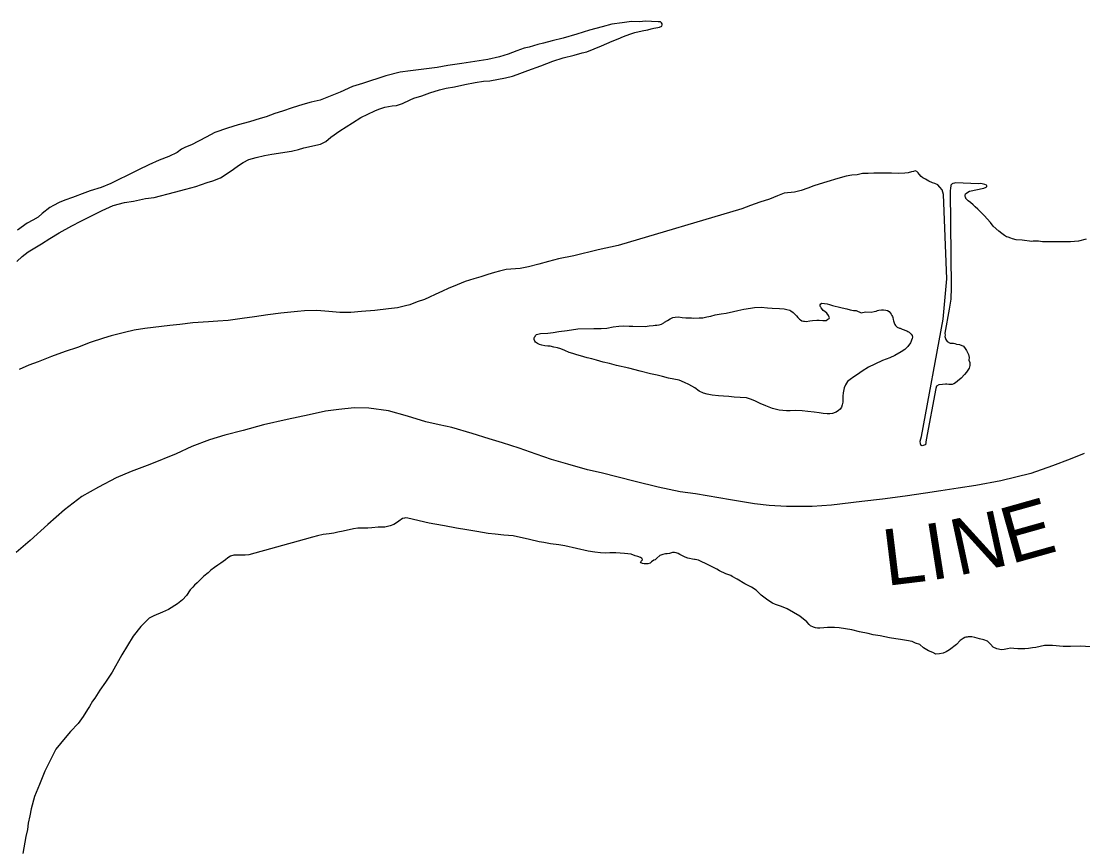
# Model space of a CAD drawing. Extents: x -939622 to -934222, y 1383701 to 1385301.
# Drawn here: x -935792.07 to -935768.16, y 1383906.21 to 1383924.82 of the extents above; entities that cross this region are included whole.
import ezdxf

# ---------------------------------------------------------------- set-up
doc = ezdxf.new("R2010")
doc.units = 0
doc.layers.add('Level 3', color=7, linetype='Continuous')
doc.layers.add('Level 9', color=7, linetype='Continuous')

msp = doc.modelspace()

# ---------------------------------------------------------------- linework, layer by layer
at = {"layer": 'Level 3'}
msp.add_lwpolyline([(-935768.121, 1383915.075), (-935768.44, 1383914.945), (-935768.84, 1383914.8), (-935769.329, 1383914.621), (-935769.999, 1383914.456), (-935770.566, 1383914.355), (-935770.963, 1383914.291), (-935771.352, 1383914.237), (-935771.698, 1383914.181), (-935772.155, 1383914.115), (-935772.664, 1383914.049), (-935773.133, 1383913.992), (-935773.818, 1383913.911), (-935774.253, 1383913.881), (-935774.833, 1383913.882), (-935775.222, 1383913.906), (-935775.55, 1383913.938), (-935776.089, 1383914.028), (-935776.882, 1383914.163), (-935777.226, 1383914.209), (-935777.717, 1383914.316), (-935778.242, 1383914.443), (-935779.004, 1383914.642), (-935779.31, 1383914.708), (-935779.754, 1383914.835), (-935780.125, 1383914.943), (-935780.469, 1383915.062), (-935780.853, 1383915.198), (-935781.225, 1383915.318), (-935781.526, 1383915.406), (-935781.909, 1383915.526), (-935782.365, 1383915.659), (-935782.653, 1383915.725), (-935782.953, 1383915.792), (-935783.37, 1383915.914), (-935783.798, 1383916.035), (-935784.24, 1383916.096), (-935784.567, 1383916.104), (-935784.918, 1383916.069), (-935785.211, 1383916.028), (-935785.583, 1383915.947), (-935786.081, 1383915.84), (-935786.614, 1383915.719), (-935787.072, 1383915.596), (-935787.482, 1383915.486), (-935787.83, 1383915.382), (-935788.227, 1383915.231), (-935788.575, 1383915.07), (-935789.172, 1383914.824), (-935789.593, 1383914.672), (-935789.93, 1383914.526), (-935790.325, 1383914.318), (-935790.707, 1383914.104), (-935791.092, 1383913.809), (-935791.473, 1383913.475), (-935791.867, 1383913.113), (-935792.184, 1383912.848)], dxfattribs=at)
at = {"layer": 'Level 9'}
for points in [[(-935779.329, 1383924.128), (-935778.997, 1383924.261), (-935778.758, 1383924.367), (-935778.622, 1383924.418), (-935778.498, 1383924.468), (-935778.358, 1383924.521), (-935778.243, 1383924.559), (-935778.148, 1383924.584), (-935778.046, 1383924.606), (-935777.951, 1383924.625), (-935777.882, 1383924.643), (-935777.82, 1383924.66), (-935777.73, 1383924.676), (-935777.689, 1383924.683), (-935777.635, 1383924.704), (-935777.634, 1383924.734), (-935777.631, 1383924.758), (-935777.644, 1383924.781), (-935777.669, 1383924.802), (-935777.723, 1383924.799), (-935777.874, 1383924.812), (-935778.006, 1383924.815), (-935778.138, 1383924.804), (-935778.325, 1383924.806), (-935778.531, 1383924.78), (-935778.761, 1383924.746), (-935778.984, 1383924.689), (-935779.267, 1383924.612), (-935779.552, 1383924.525), (-935779.861, 1383924.435), (-935780.111, 1383924.371), (-935780.301, 1383924.321), (-935780.429, 1383924.292), (-935780.628, 1383924.233), (-935780.738, 1383924.205), (-935780.901, 1383924.147), (-935781.097, 1383924.07), (-935781.293, 1383924.014), (-935781.555, 1383923.956), (-935782.146, 1383923.866), (-935782.46, 1383923.815), (-935782.696, 1383923.775), (-935782.998, 1383923.736), (-935783.3, 1383923.7), (-935783.53, 1383923.664), (-935783.855, 1383923.588), (-935784.38, 1383923.414), (-935784.605, 1383923.342), (-935784.883, 1383923.219), (-935785.336, 1383923.039), (-935785.538, 1383922.995), (-935785.722, 1383922.939), (-935785.966, 1383922.863), (-935786.186, 1383922.791), (-935786.358, 1383922.734), (-935786.55, 1383922.663), (-935786.684, 1383922.621), (-935786.927, 1383922.551), (-935787.183, 1383922.484), (-935787.42, 1383922.403), (-935787.708, 1383922.307), (-935787.906, 1383922.206), (-935788.235, 1383922.033), (-935788.372, 1383921.98), (-935788.457, 1383921.931), (-935788.559, 1383921.861), (-935788.745, 1383921.769), (-935788.964, 1383921.685), (-935789.194, 1383921.58), (-935789.43, 1383921.468), (-935789.681, 1383921.338), (-935789.872, 1383921.246), (-935790.052, 1383921.158), (-935790.268, 1383921.071), (-935790.515, 1383920.992), (-935790.639, 1383920.948), (-935790.915, 1383920.847), (-935791.083, 1383920.78), (-935791.214, 1383920.73), (-935791.343, 1383920.667), (-935791.423, 1383920.619), (-935791.594, 1383920.48), (-935791.691, 1383920.401), (-935791.805, 1383920.336), (-935791.932, 1383920.265), (-935792.154, 1383920.106)], [(-935792.168, 1383919.398), (-935792.046, 1383919.517), (-935791.912, 1383919.622), (-935791.613, 1383919.802), (-935791.422, 1383919.918), (-935791.211, 1383920.047), (-935790.931, 1383920.202), (-935790.725, 1383920.313), (-935790.531, 1383920.408), (-935790.248, 1383920.551), (-935789.997, 1383920.663), (-935789.741, 1383920.728), (-935789.538, 1383920.763), (-935789.27, 1383920.822), (-935789.072, 1383920.847), (-935788.617, 1383920.962), (-935788.361, 1383921.035), (-935788.132, 1383921.092), (-935787.88, 1383921.183), (-935787.75, 1383921.222), (-935787.581, 1383921.289), (-935787.449, 1383921.372), (-935787.288, 1383921.481), (-935787.174, 1383921.561), (-935787.072, 1383921.631), (-935786.945, 1383921.696), (-935786.773, 1383921.748), (-935786.588, 1383921.791), (-935786.424, 1383921.819), (-935785.979, 1383921.888), (-935785.949, 1383921.898), (-935785.821, 1383921.927), (-935785.705, 1383921.962), (-935785.33, 1383922.046), (-935785.209, 1383922.105), (-935785.092, 1383922.2), (-935784.891, 1383922.349), (-935784.609, 1383922.523), (-935784.419, 1383922.648), (-935784.103, 1383922.799), (-935784.011, 1383922.835), (-935783.881, 1383922.877), (-935783.711, 1383922.907), (-935783.612, 1383922.92), (-935783.481, 1383922.962), (-935783.307, 1383923.044), (-935783.222, 1383923.08), (-935783.046, 1383923.135), (-935782.863, 1383923.203), (-935782.649, 1383923.268), (-935782.494, 1383923.305), (-935782.306, 1383923.336), (-935782.077, 1383923.387), (-935781.841, 1383923.436), (-935781.659, 1383923.464), (-935781.512, 1383923.476), (-935781.157, 1383923.541), (-935781.002, 1383923.58), (-935780.895, 1383923.612), (-935780.653, 1383923.705), (-935780.365, 1383923.813), (-935780.096, 1383923.917), (-935779.861, 1383923.99), (-935779.614, 1383924.05), (-935779.43, 1383924.1), (-935779.329, 1383924.128)], [(-935771.421, 1383921.127), (-935771.491, 1383921.157), (-935771.543, 1383921.173), (-935771.626, 1383921.215), (-935771.697, 1383921.254), (-935771.758, 1383921.288), (-935771.795, 1383921.32), (-935771.842, 1383921.369), (-935771.862, 1383921.401), (-935771.893, 1383921.427), (-935771.929, 1383921.441), (-935771.968, 1383921.433), (-935772.01, 1383921.419), (-935772.087, 1383921.401), (-935772.165, 1383921.389), (-935772.306, 1383921.387), (-935772.465, 1383921.389), (-935772.61, 1383921.393), (-935772.724, 1383921.391), (-935772.859, 1383921.389), (-935772.988, 1383921.384), (-935773.114, 1383921.382), (-935773.236, 1383921.356), (-935773.356, 1383921.345), (-935773.487, 1383921.325), (-935773.672, 1383921.275), (-935773.921, 1383921.199), (-935774.096, 1383921.144), (-935774.212, 1383921.107), (-935774.351, 1383921.056), (-935774.497, 1383921.005), (-935774.619, 1383920.973), (-935774.648, 1383920.963), (-935774.879, 1383920.939), (-935775.033, 1383920.879), (-935775.216, 1383920.808), (-935775.433, 1383920.736), (-935775.637, 1383920.662), (-935775.836, 1383920.591), (-935778.619, 1383919.765), (-935779.069, 1383919.663), (-935779.617, 1383919.527), (-935779.966, 1383919.459), (-935780.192, 1383919.401), (-935780.412, 1383919.342), (-935780.644, 1383919.284), (-935780.829, 1383919.247), (-935781.144, 1383919.222), (-935781.292, 1383919.186), (-935781.408, 1383919.155), (-935781.56, 1383919.11), (-935781.714, 1383919.058), (-935781.872, 1383919.01), (-935782.071, 1383918.951), (-935782.245, 1383918.878), (-935782.449, 1383918.792), (-935782.582, 1383918.732), (-935782.744, 1383918.659), (-935782.874, 1383918.6), (-935782.983, 1383918.548), (-935783.146, 1383918.49), (-935783.315, 1383918.426), (-935783.416, 1383918.401), (-935783.595, 1383918.355), (-935783.792, 1383918.332), (-935784.101, 1383918.296), (-935784.403, 1383918.272), (-935784.643, 1383918.25), (-935784.892, 1383918.253), (-935785.137, 1383918.276), (-935785.411, 1383918.295), (-935785.684, 1383918.293), (-935785.846, 1383918.278), (-935786.22, 1383918.239), (-935786.51, 1383918.198), (-935786.815, 1383918.156), (-935787.09, 1383918.115), (-935787.41, 1383918.075), (-935787.643, 1383918.054), (-935787.853, 1383918.039), (-935788.201, 1383918.019), (-935788.497, 1383917.981), (-935788.718, 1383917.957), (-935789.281, 1383917.893), (-935789.526, 1383917.853), (-935789.746, 1383917.799), (-935790.044, 1383917.727), (-935790.213, 1383917.675), (-935790.513, 1383917.576), (-935790.803, 1383917.465), (-935791.079, 1383917.373), (-935791.384, 1383917.262), (-935791.686, 1383917.144), (-935791.899, 1383917.064), (-935792.112, 1383916.965)], [(-935769.306, 1383919.853), (-935769.524, 1383919.88), (-935769.657, 1383919.893), (-935769.736, 1383919.914), (-935769.778, 1383919.924), (-935769.836, 1383919.952), (-935769.873, 1383919.96), (-935769.922, 1383919.985), (-935769.981, 1383920.031), (-935770.046, 1383920.085), (-935770.176, 1383920.195), (-935770.234, 1383920.283), (-935770.309, 1383920.361), (-935770.372, 1383920.431), (-935770.435, 1383920.5), (-935770.519, 1383920.578), (-935770.581, 1383920.636), (-935770.628, 1383920.682), (-935770.687, 1383920.731), (-935770.737, 1383920.765), (-935770.777, 1383920.806), (-935770.783, 1383920.809), (-935770.8, 1383920.85), (-935770.804, 1383920.865), (-935770.805, 1383920.895), (-935770.794, 1383920.923), (-935770.777, 1383920.944), (-935770.747, 1383920.964), (-935770.706, 1383920.983), (-935770.387, 1383921.053), (-935770.328, 1383921.073), (-935770.317, 1383921.089), (-935770.314, 1383921.104), (-935770.327, 1383921.122), (-935770.358, 1383921.139), (-935770.451, 1383921.156), (-935770.505, 1383921.151), (-935771.023, 1383921.172), (-935771.047, 1383921.165), (-935771.086, 1383921.158), (-935771.101, 1383921.154), (-935771.115, 1383921.136), (-935771.126, 1383921.12), (-935771.131, 1383921.099), (-935771.136, 1383921.06), (-935771.139, 1383920.987), (-935771.12, 1383918.812), (-935771.128, 1383918.553), (-935771.164, 1383918.329), (-935771.26, 1383917.786), (-935771.258, 1383917.744), (-935771.263, 1383917.711), (-935771.256, 1383917.687), (-935771.239, 1383917.645), (-935771.226, 1383917.622), (-935771.207, 1383917.601), (-935771.143, 1383917.559), (-935771.068, 1383917.559), (-935771.034, 1383917.557), (-935771.001, 1383917.54), (-935770.934, 1383917.534), (-935770.846, 1383917.495), (-935770.802, 1383917.443), (-935770.772, 1383917.393), (-935770.759, 1383917.366), (-935770.733, 1383917.307), (-935770.718, 1383917.239), (-935770.719, 1383917.178), (-935770.702, 1383917.125), (-935770.699, 1383917.059), (-935770.715, 1383917.001), (-935770.726, 1383916.973), (-935770.772, 1383916.911), (-935770.82, 1383916.855), (-935770.898, 1383916.771), (-935770.974, 1383916.702), (-935771.023, 1383916.667), (-935771.059, 1383916.644), (-935771.097, 1383916.628), (-935771.172, 1383916.628), (-935771.221, 1383916.635), (-935771.251, 1383916.637), (-935771.316, 1383916.628), (-935771.4, 1383916.622), (-935771.447, 1383916.59), (-935771.469, 1383916.541), (-935771.682, 1383915.386), (-935771.702, 1383915.273), (-935771.729, 1383915.263), (-935771.752, 1383915.253), (-935771.773, 1383915.249), (-935771.798, 1383915.258), (-935771.811, 1383915.296), (-935771.816, 1383915.35), (-935771.787, 1383915.46), (-935771.302, 1383918.1), (-935771.221, 1383919.01), (-935771.292, 1383920.912), (-935771.321, 1383921.016), (-935771.377, 1383921.074), (-935771.421, 1383921.127)], [(-935768.079, 1383919.901), (-935768.255, 1383919.861), (-935768.434, 1383919.842), (-935768.594, 1383919.842), (-935768.729, 1383919.842), (-935768.9, 1383919.848), (-935769.063, 1383919.847), (-935769.156, 1383919.856), (-935769.271, 1383919.86), (-935769.306, 1383919.853)], [(-935777.648, 1383917.988), (-935777.592, 1383918.017), (-935777.575, 1383918.033), (-935777.513, 1383918.072), (-935777.454, 1383918.107), (-935777.387, 1383918.14), (-935777.339, 1383918.148), (-935777.261, 1383918.151), (-935777.182, 1383918.136), (-935777.101, 1383918.13), (-935776.968, 1383918.132), (-935776.914, 1383918.128), (-935776.8, 1383918.13), (-935776.713, 1383918.133), (-935776.627, 1383918.155), (-935776.537, 1383918.17), (-935776.433, 1383918.199), (-935776.299, 1383918.222), (-935776.188, 1383918.241), (-935776.027, 1383918.272), (-935775.929, 1383918.294), (-935775.792, 1383918.326), (-935775.64, 1383918.35), (-935775.553, 1383918.363), (-935775.403, 1383918.369), (-935775.255, 1383918.36), (-935775.153, 1383918.349), (-935774.99, 1383918.34), (-935774.885, 1383918.335), (-935774.821, 1383918.319), (-935774.757, 1383918.304), (-935774.733, 1383918.287), (-935774.68, 1383918.256), (-935774.649, 1383918.224), (-935774.605, 1383918.181), (-935774.576, 1383918.137), (-935774.539, 1383918.105), (-935774.511, 1383918.085), (-935774.483, 1383918.065), (-935774.447, 1383918.057), (-935774.426, 1383918.055), (-935774.384, 1383918.051), (-935774.303, 1383918.066), (-935774.243, 1383918.074), (-935774.15, 1383918.078), (-935774.09, 1383918.08), (-935774.009, 1383918.075), (-935773.985, 1383918.07), (-935773.964, 1383918.07), (-935773.937, 1383918.075), (-935773.902, 1383918.1), (-935773.866, 1383918.116), (-935773.861, 1383918.135), (-935773.881, 1383918.188), (-935773.919, 1383918.235), (-935773.969, 1383918.278), (-935774, 1383918.301), (-935774.022, 1383918.318), (-935774.05, 1383918.356), (-935774.057, 1383918.371), (-935774.063, 1383918.383), (-935774.07, 1383918.406), (-935774.068, 1383918.428), (-935774.054, 1383918.449), (-935774.03, 1383918.459), (-935773.973, 1383918.455), (-935773.915, 1383918.449), (-935773.858, 1383918.433), (-935773.791, 1383918.411), (-935773.733, 1383918.393), (-935773.666, 1383918.377), (-935773.572, 1383918.36), (-935773.472, 1383918.337), (-935773.393, 1383918.313), (-935773.318, 1383918.301), (-935773.257, 1383918.294)], [(-935773.257, 1383918.294), (-935773.147, 1383918.247), (-935773.049, 1383918.269), (-935772.919, 1383918.262), (-935772.854, 1383918.274), (-935772.812, 1383918.282), (-935772.779, 1383918.295), (-935772.747, 1383918.302), (-935772.69, 1383918.31), (-935772.645, 1383918.312), (-935772.594, 1383918.308), (-935772.557, 1383918.298), (-935772.517, 1383918.272), (-935772.492, 1383918.246), (-935772.47, 1383918.214), (-935772.454, 1383918.184), (-935772.441, 1383918.161), (-935772.437, 1383918.137), (-935772.429, 1383918.098), (-935772.422, 1383918.065), (-935772.405, 1383918.018), (-935772.389, 1383917.985), (-935772.372, 1383917.956), (-935772.335, 1383917.921), (-935772.283, 1383917.899), (-935772.271, 1383917.897), (-935772.222, 1383917.877), (-935772.176, 1383917.864), (-935772.161, 1383917.856), (-935772.118, 1383917.836), (-935772.094, 1383917.828), (-935772.082, 1383917.82), (-935772.066, 1383917.811), (-935772.041, 1383917.788), (-935772.019, 1383917.762), (-935772, 1383917.733), (-935771.99, 1383917.697), (-935771.997, 1383917.664), (-935772.036, 1383917.569), (-935772.099, 1383917.488), (-935772.165, 1383917.416), (-935772.247, 1383917.368), (-935772.388, 1383917.287), (-935772.5, 1383917.234), (-935772.669, 1383917.17), (-935772.843, 1383917.088), (-935772.982, 1383917.017), (-935773.122, 1383916.927), (-935773.231, 1383916.859), (-935773.316, 1383916.802), (-935773.398, 1383916.744), (-935773.456, 1383916.7), (-935773.501, 1383916.626), (-935773.531, 1383916.552), (-935773.551, 1383916.443), (-935773.563, 1383916.368), (-935773.563, 1383916.289), (-935773.564, 1383916.229), (-935773.573, 1383916.169), (-935773.59, 1383916.12), (-935773.618, 1383916.077), (-935773.656, 1383916.045), (-935773.708, 1383916.01), (-935773.732, 1383916), (-935773.791, 1383915.979), (-935773.854, 1383915.971), (-935773.917, 1383915.968), (-935774.002, 1383915.98), (-935774.093, 1383915.995), (-935774.207, 1383916.008), (-935774.346, 1383916.021), (-935774.479, 1383916.033), (-935774.623, 1383916.043), (-935774.749, 1383916.035), (-935774.828, 1383916.038), (-935774.993, 1383916.052), (-935775.148, 1383916.088), (-935775.295, 1383916.152), (-935775.423, 1383916.204), (-935775.53, 1383916.254), (-935775.616, 1383916.293), (-935775.729, 1383916.333), (-935775.873, 1383916.337), (-935776.006, 1383916.346), (-935776.126, 1383916.36), (-935776.247, 1383916.364), (-935776.361, 1383916.371), (-935776.503, 1383916.387), (-935776.618, 1383916.409), (-935776.703, 1383916.433), (-935776.795, 1383916.481), (-935776.897, 1383916.555), (-935777.027, 1383916.631), (-935777.13, 1383916.672), (-935777.25, 1383916.725), (-935777.371, 1383916.75), (-935777.489, 1383916.775), (-935777.623, 1383916.812), (-935777.741, 1383916.838), (-935777.896, 1383916.871), (-935778.123, 1383916.928)], [(-935778.123, 1383916.928), (-935778.384, 1383916.996), (-935778.657, 1383917.06), (-935778.818, 1383917.102), (-935778.961, 1383917.136), (-935779.11, 1383917.178), (-935779.213, 1383917.21), (-935779.319, 1383917.233), (-935779.468, 1383917.275), (-935779.556, 1383917.302), (-935779.642, 1383917.325), (-935779.727, 1383917.349), (-935779.825, 1383917.396), (-935779.913, 1383917.435), (-935779.989, 1383917.453), (-935780.074, 1383917.471), (-935780.153, 1383917.492), (-935780.207, 1383917.496), (-935780.277, 1383917.505), (-935780.343, 1383917.517), (-935780.392, 1383917.533), (-935780.441, 1383917.556), (-935780.481, 1383917.587), (-935780.5, 1383917.607), (-935780.514, 1383917.643), (-935780.515, 1383917.667), (-935780.512, 1383917.676), (-935780.507, 1383917.697), (-935780.495, 1383917.713), (-935780.484, 1383917.731), (-935780.458, 1383917.754), (-935780.428, 1383917.767), (-935780.369, 1383917.778), (-935780.204, 1383917.788), (-935780.087, 1383917.804), (-935779.956, 1383917.828), (-935779.77, 1383917.847), (-935779.531, 1383917.881), (-935779.171, 1383917.892), (-935779.006, 1383917.892), (-935778.877, 1383917.9), (-935778.731, 1383917.927), (-935778.608, 1383917.944), (-935778.497, 1383917.951), (-935778.377, 1383917.947), (-935778.292, 1383917.945), (-935778.013, 1383917.938), (-935777.92, 1383917.95), (-935777.836, 1383917.96), (-935777.791, 1383917.964), (-935777.752, 1383917.969), (-935777.699, 1383917.977), (-935777.648, 1383917.988)], [(-935777.748, 1383912.72), (-935777.791, 1383912.679), (-935777.815, 1383912.669), (-935777.871, 1383912.637), (-935777.902, 1383912.605), (-935777.95, 1383912.591), (-935777.992, 1383912.587), (-935778.034, 1383912.591), (-935778.073, 1383912.596), (-935778.092, 1383912.601), (-935778.113, 1383912.615), (-935778.116, 1383912.618), (-935778.111, 1383912.636), (-935778.102, 1383912.649), (-935778.082, 1383912.671), (-935778.074, 1383912.683), (-935778.078, 1383912.707), (-935778.096, 1383912.718), (-935778.118, 1383912.729), (-935778.179, 1383912.751), (-935778.24, 1383912.773), (-935778.328, 1383912.805), (-935778.479, 1383912.823), (-935778.575, 1383912.826), (-935778.675, 1383912.834), (-935778.807, 1383912.834), (-935778.897, 1383912.828), (-935779.017, 1383912.838), (-935779.144, 1383912.854), (-935779.299, 1383912.878), (-935779.826, 1383912.993), (-935779.962, 1383913.015), (-935780.143, 1383913.038), (-935780.295, 1383913.068), (-935780.401, 1383913.088), (-935780.619, 1383913.136), (-935780.986, 1383913.218), (-935781.197, 1383913.234), (-935781.396, 1383913.256), (-935781.553, 1383913.274), (-935781.804, 1383913.318), (-935782.031, 1383913.357), (-935782.267, 1383913.396), (-935782.533, 1383913.443), (-935782.751, 1383913.482), (-935782.882, 1383913.507), (-935783.361, 1383913.618), (-935783.409, 1383913.625), (-935783.436, 1383913.621), (-935783.478, 1383913.61), (-935783.563, 1383913.553), (-935783.641, 1383913.495), (-935783.674, 1383913.476), (-935783.76, 1383913.442), (-935783.876, 1383913.417), (-935783.975, 1383913.416), (-935784.026, 1383913.414), (-935784.17, 1383913.399), (-935784.26, 1383913.396), (-935784.488, 1383913.393), (-935784.581, 1383913.38), (-935784.813, 1383913.326), (-935784.938, 1383913.303), (-935785.028, 1383913.281), (-935785.132, 1383913.268), (-935785.267, 1383913.247), (-935785.395, 1383913.218), (-935785.511, 1383913.187), (-935785.695, 1383913.14), (-935786.938, 1383912.79), (-935787.025, 1383912.784), (-935787.076, 1383912.785), (-935787.151, 1383912.788), (-935787.28, 1383912.783), (-935787.354, 1383912.765), (-935787.416, 1383912.723), (-935787.465, 1383912.676), (-935787.576, 1383912.602), (-935787.641, 1383912.561), (-935787.717, 1383912.506), (-935787.796, 1383912.443), (-935787.86, 1383912.389), (-935787.953, 1383912.311), (-935787.982, 1383912.282), (-935788.005, 1383912.26), (-935788.103, 1383912.16), (-935788.164, 1383912.107), (-935788.204, 1383912.066), (-935788.265, 1383912), (-935788.347, 1383911.877), (-935788.434, 1383911.78), (-935788.547, 1383911.685), (-935788.753, 1383911.56), (-935788.889, 1383911.5), (-935789.081, 1383911.42), (-935789.19, 1383911.365), (-935789.375, 1383911.174), (-935789.549, 1383910.956), (-935789.8, 1383910.54), (-935790.017, 1383910.152), (-935790.167, 1383909.926)], [(-935769.015, 1383910.747), (-935769.119, 1383910.728), (-935769.214, 1383910.703), (-935769.286, 1383910.695), (-935769.379, 1383910.685), (-935769.463, 1383910.672), (-935769.616, 1383910.672), (-935769.712, 1383910.681), (-935769.782, 1383910.687), (-935769.853, 1383910.675), (-935769.925, 1383910.66), (-935769.985, 1383910.655), (-935770.094, 1383910.672), (-935770.171, 1383910.714), (-935770.233, 1383910.78), (-935770.299, 1383910.844), (-935770.381, 1383910.874), (-935770.484, 1383910.903), (-935770.588, 1383910.929), (-935770.657, 1383910.944), (-935770.706, 1383910.948), (-935770.739, 1383910.947), (-935770.762, 1383910.94), (-935770.789, 1383910.936), (-935770.81, 1383910.929), (-935770.851, 1383910.91), (-935770.916, 1383910.862), (-935770.999, 1383910.771), (-935771.157, 1383910.654), (-935771.233, 1383910.603), (-935771.301, 1383910.576), (-935771.385, 1383910.56), (-935771.463, 1383910.557), (-935771.536, 1383910.588), (-935771.634, 1383910.632), (-935771.745, 1383910.697), (-935771.829, 1383910.772), (-935771.926, 1383910.804), (-935772, 1383910.843), (-935772.13, 1383910.859), (-935772.263, 1383910.881), (-935772.369, 1383910.898), (-935772.508, 1383910.925), (-935772.72, 1383910.965), (-935772.874, 1383910.992), (-935772.992, 1383911.018), (-935773.183, 1383911.058), (-935773.356, 1383911.1), (-935773.499, 1383911.127), (-935773.641, 1383911.145), (-935773.749, 1383911.156), (-935773.854, 1383911.155), (-935773.908, 1383911.153), (-935773.989, 1383911.147), (-935774.082, 1383911.14), (-935774.133, 1383911.141), (-935774.176, 1383911.145), (-935774.224, 1383911.159), (-935774.289, 1383911.192), (-935774.317, 1383911.221), (-935774.37, 1383911.282), (-935774.529, 1383911.411), (-935774.817, 1383911.572), (-935774.94, 1383911.627), (-935775.077, 1383911.676), (-935775.147, 1383911.703), (-935775.249, 1383911.768), (-935775.401, 1383911.886), (-935775.476, 1383911.958), (-935775.513, 1383911.995), (-935775.618, 1383912.064), (-935775.768, 1383912.139), (-935775.941, 1383912.243), (-935776.057, 1383912.302), (-935776.082, 1383912.325), (-935776.198, 1383912.366), (-935776.339, 1383912.435), (-935776.4, 1383912.469), (-935776.532, 1383912.536), (-935776.606, 1383912.578), (-935776.783, 1383912.659), (-935776.811, 1383912.67), (-935776.887, 1383912.688), (-935776.902, 1383912.687), (-935776.944, 1383912.694), (-935777.014, 1383912.71), (-935777.05, 1383912.72), (-935777.114, 1383912.739), (-935777.154, 1383912.764), (-935777.234, 1383912.8), (-935777.271, 1383912.82), (-935777.313, 1383912.836), (-935777.35, 1383912.844), (-935777.395, 1383912.848), (-935777.422, 1383912.838), (-935777.469, 1383912.821), (-935777.52, 1383912.816), (-935777.556, 1383912.815), (-935777.612, 1383912.797), (-935777.681, 1383912.774), (-935777.748, 1383912.72)], [(-935767.986, 1383910.716), (-935768.2, 1383910.734), (-935768.431, 1383910.728), (-935768.596, 1383910.725), (-935768.834, 1383910.748), (-935769.015, 1383910.747)], [(-935790.167, 1383909.926), (-935790.295, 1383909.744), (-935790.414, 1383909.559), (-935790.46, 1383909.494), (-935790.533, 1383909.376), (-935790.573, 1383909.308), (-935790.672, 1383909.151), (-935790.786, 1383908.993), (-935790.956, 1383908.812), (-935791.082, 1383908.671), (-935791.286, 1383908.416), (-935791.54, 1383907.919), (-935791.654, 1383907.616), (-935791.77, 1383907.347), (-935791.843, 1383907.07), (-935791.873, 1383906.912), (-935791.911, 1383906.745), (-935791.93, 1383906.603), (-935791.963, 1383906.442), (-935792.035, 1383906.06)]]:
    msp.add_lwpolyline(points, dxfattribs=at)

# ---------------------------------------------------------------- texts
at = {"layer": 'Level 3'}
for s, rotation, p in [('E', 15.7347, (-935769.777, 1383912.58)), ('N', 12.1362, (-935770.975, 1383912.317)), ('I', 8.9159, (-935771.589, 1383912.215)), ('L', 6.9306, (-935772.581, 1383912.091))]:
    msp.add_text(s, height=1.267, rotation=rotation, dxfattribs=at).set_placement(p)

doc.saveas('drawing.dxf')
